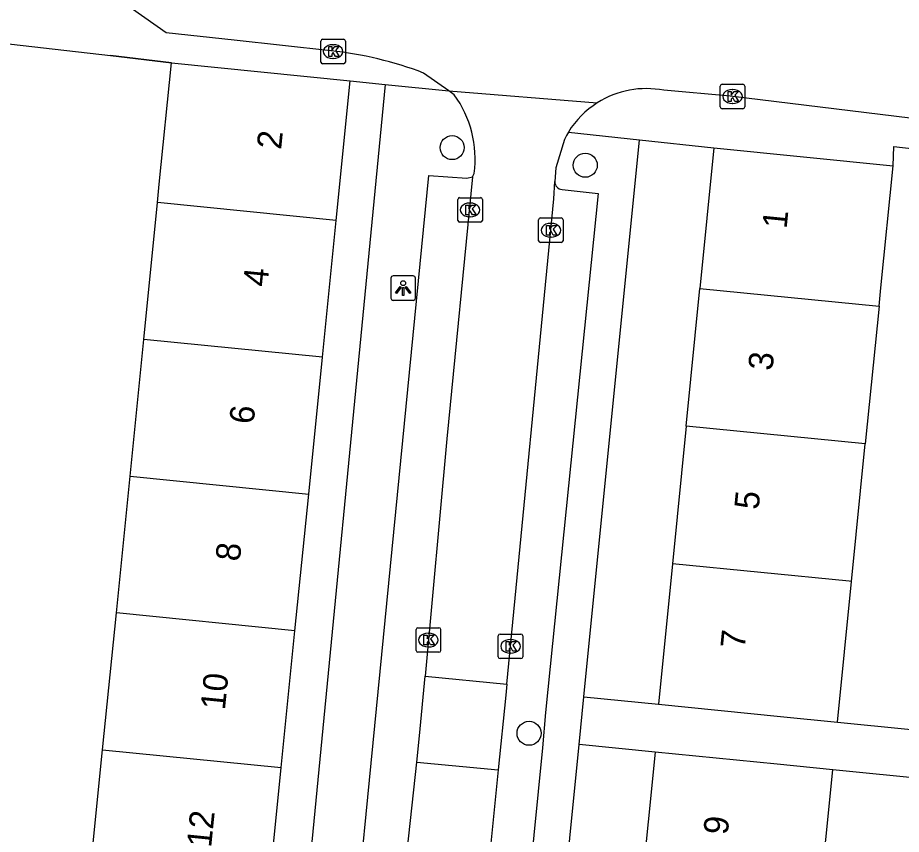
# Model space of a CAD drawing. Extents: x 162250 to 162654, y 380744 to 381605.
# Drawn here: x 162303.66 to 162339.7, y 380867.49 to 380900.78 of the extents above; entities that cross this region are included whole.
import ezdxf

# ---------------------------------------------------------------- set-up
doc = ezdxf.new("R2010")
doc.units = 0
for name, color, linetype in [('IMGEO_Boom', 7, 'Continuous'), ('IMGEO_Kolk', 7, 'Continuous'), ('IMGEO_Lichtpunt', 7, 'Continuous'), ('IMGEO_Muur', 7, 'Continuous'), ('IMGEO_Pand', 7, 'Continuous'), ('IMGEO_Pand_nummerreeks', 7, 'Continuous'), ('IMGEO_Rijbaan_lokaal_open', 7, 'Continuous'), ('IMGEO_Voetpad_open', 7, 'Continuous')]:
    doc.layers.add(name, color=color, linetype=linetype)

msp = doc.modelspace()

# ---------------------------------------------------------------- linework, layer by layer
at = {"layer": 'IMGEO_Boom'}
for centre in [(162321.376, 380895.484), (162326.808, 380894.764), (162324.515, 380871.605)]:
    msp.add_circle(centre, 0.489, dxfattribs=at)
at = {"layer": 'IMGEO_Kolk'}
for p, q in [((162316.022, 380898.974), (162316.022, 380899.826)), ((162316.097, 380899.9), (162316.949, 380899.9)), ((162316.51, 380899.68), (162316.535, 380899.68)), ((162317.023, 380899.826), (162317.023, 380898.974)), ((162316.533, 380899.12), (162316.508, 380899.12)), ((162316.949, 380898.9), (162316.097, 380898.9)), ((162332.314, 380897.143), (162332.314, 380897.995)), ((162332.389, 380898.069), (162333.241, 380898.069)), ((162332.802, 380897.849), (162332.827, 380897.849)), ((162333.315, 380897.995), (162333.315, 380897.143)), ((162332.825, 380897.289), (162332.8, 380897.289)), ((162333.241, 380897.069), (162332.389, 380897.069)), ((162321.609, 380892.517), (162321.609, 380893.369)), ((162321.684, 380893.443), (162322.536, 380893.443)), ((162322.097, 380893.223), (162322.122, 380893.223)), ((162322.61, 380893.369), (162322.61, 380892.517)), ((162322.536, 380892.443), (162321.684, 380892.443)), ((162322.12, 380892.663), (162322.095, 380892.663)), ((162324.905, 380891.689), (162324.905, 380892.541)), ((162324.98, 380892.615), (162325.832, 380892.615)), ((162325.906, 380892.541), (162325.906, 380891.689)), ((162325.393, 380892.395), (162325.418, 380892.395)), ((162325.416, 380891.835), (162325.391, 380891.835)), ((162325.832, 380891.615), (162324.98, 380891.615)), ((162319.909, 380874.981), (162319.909, 380875.833)), ((162319.984, 380875.907), (162320.836, 380875.907)), ((162320.91, 380875.833), (162320.91, 380874.981)), ((162320.397, 380875.687), (162320.422, 380875.687)), ((162323.259, 380874.725), (162323.259, 380875.577)), ((162323.334, 380875.651), (162324.186, 380875.651)), ((162324.26, 380875.577), (162324.26, 380874.725)), ((162320.42, 380875.127), (162320.395, 380875.127)), ((162323.747, 380875.431), (162323.772, 380875.431)), ((162320.836, 380874.907), (162319.984, 380874.907)), ((162323.77, 380874.871), (162323.745, 380874.871)), ((162324.186, 380874.651), (162323.334, 380874.651))]:
    msp.add_line(p, q, dxfattribs=at)
for points in [[(162316.022, 380898.974), (162316.022, 380899.826)], [(162316.097, 380899.9), (162316.949, 380899.9)], [(162317.023, 380899.826), (162317.023, 380898.974)], [(162316.343, 380899.6), (162316.466, 380899.6), (162316.466, 380899.449), (162316.596, 380899.6), (162316.76, 380899.6), (162316.614, 380899.449), (162316.767, 380899.2), (162316.615, 380899.2), (162316.53, 380899.364), (162316.466, 380899.297), (162316.466, 380899.2), (162316.343, 380899.2), (162316.343, 380899.6)], [(162316.949, 380898.9), (162316.097, 380898.9)], [(162332.314, 380897.143), (162332.314, 380897.995)], [(162332.389, 380898.069), (162333.241, 380898.069)], [(162333.315, 380897.995), (162333.315, 380897.143)], [(162332.635, 380897.769), (162332.758, 380897.769), (162332.758, 380897.618), (162332.888, 380897.769), (162333.052, 380897.769), (162332.906, 380897.618), (162333.059, 380897.369), (162332.907, 380897.369), (162332.822, 380897.533), (162332.758, 380897.466), (162332.758, 380897.369), (162332.635, 380897.369), (162332.635, 380897.769)], [(162333.241, 380897.069), (162332.389, 380897.069)], [(162321.609, 380892.517), (162321.609, 380893.369)], [(162321.684, 380893.443), (162322.536, 380893.443)], [(162321.93, 380893.143), (162322.053, 380893.143), (162322.053, 380892.992), (162322.183, 380893.143), (162322.347, 380893.143), (162322.201, 380892.992), (162322.354, 380892.743), (162322.202, 380892.743), (162322.117, 380892.907), (162322.053, 380892.84), (162322.053, 380892.743), (162321.93, 380892.743), (162321.93, 380893.143)], [(162322.61, 380893.369), (162322.61, 380892.517)], [(162322.536, 380892.443), (162321.684, 380892.443)], [(162324.905, 380891.689), (162324.905, 380892.541)], [(162324.98, 380892.615), (162325.832, 380892.615)], [(162325.906, 380892.541), (162325.906, 380891.689)], [(162325.226, 380892.315), (162325.349, 380892.315), (162325.349, 380892.164), (162325.479, 380892.315), (162325.643, 380892.315), (162325.497, 380892.164), (162325.65, 380891.915), (162325.498, 380891.915), (162325.413, 380892.079), (162325.349, 380892.012), (162325.349, 380891.915), (162325.226, 380891.915), (162325.226, 380892.315)], [(162325.832, 380891.615), (162324.98, 380891.615)], [(162319.909, 380874.981), (162319.909, 380875.833)], [(162319.984, 380875.907), (162320.836, 380875.907)], [(162320.91, 380875.833), (162320.91, 380874.981)], [(162320.23, 380875.607), (162320.353, 380875.607), (162320.353, 380875.456), (162320.483, 380875.607), (162320.647, 380875.607), (162320.501, 380875.456), (162320.654, 380875.207), (162320.502, 380875.207), (162320.417, 380875.371), (162320.353, 380875.304), (162320.353, 380875.207), (162320.23, 380875.207), (162320.23, 380875.607)], [(162323.259, 380874.725), (162323.259, 380875.577)], [(162323.334, 380875.651), (162324.186, 380875.651)], [(162324.26, 380875.577), (162324.26, 380874.725)], [(162323.58, 380875.351), (162323.703, 380875.351), (162323.703, 380875.2), (162323.833, 380875.351), (162323.997, 380875.351), (162323.851, 380875.2), (162324.004, 380874.951), (162323.852, 380874.951), (162323.767, 380875.115), (162323.703, 380875.048), (162323.703, 380874.951), (162323.58, 380874.951), (162323.58, 380875.351)], [(162320.836, 380874.907), (162319.984, 380874.907)], [(162324.186, 380874.651), (162323.334, 380874.651)]]:
    msp.add_lwpolyline(points, dxfattribs=at)
for centre, start, end in [((162316.099, 380899.824), 91.552, 178.448), ((162316.099, 380899.824), 91.552, 178.448), ((162316.947, 380899.824), 1.552, 88.448), ((162316.947, 380899.824), 1.552, 88.448), ((162316.099, 380898.976), 181.552, 268.448), ((162316.099, 380898.976), 181.552, 268.448), ((162316.947, 380898.976), 271.552, 358.448), ((162316.947, 380898.976), 271.552, 358.448), ((162332.391, 380897.993), 91.552, 178.448), ((162332.391, 380897.993), 91.552, 178.448), ((162333.239, 380897.993), 1.552, 88.448), ((162333.239, 380897.993), 1.552, 88.448), ((162332.391, 380897.145), 181.552, 268.448), ((162332.391, 380897.145), 181.552, 268.448), ((162333.239, 380897.145), 271.552, 358.448), ((162333.239, 380897.145), 271.552, 358.448), ((162321.686, 380893.367), 91.552, 178.448), ((162321.686, 380893.367), 91.552, 178.448), ((162322.534, 380893.367), 1.552, 88.448), ((162322.534, 380893.367), 1.552, 88.448), ((162321.686, 380892.519), 181.552, 268.448), ((162321.686, 380892.519), 181.552, 268.448), ((162322.534, 380892.519), 271.552, 358.448), ((162322.534, 380892.519), 271.552, 358.448), ((162324.982, 380892.539), 91.552, 178.448), ((162324.982, 380892.539), 91.552, 178.448), ((162325.83, 380892.539), 1.552, 88.448), ((162325.83, 380892.539), 1.552, 88.448), ((162324.982, 380891.691), 181.552, 268.448), ((162324.982, 380891.691), 181.552, 268.448), ((162325.83, 380891.691), 271.552, 358.448), ((162325.83, 380891.691), 271.552, 358.448), ((162319.986, 380875.831), 91.552, 178.448), ((162319.986, 380875.831), 91.552, 178.448), ((162320.834, 380875.831), 1.552, 88.448), ((162320.834, 380875.831), 1.552, 88.448), ((162323.336, 380875.575), 91.552, 178.448), ((162323.336, 380875.575), 91.552, 178.448), ((162324.184, 380875.575), 1.552, 88.448), ((162324.184, 380875.575), 1.552, 88.448), ((162319.986, 380874.983), 181.552, 268.448), ((162319.986, 380874.983), 181.552, 268.448), ((162320.834, 380874.983), 271.552, 358.448), ((162320.834, 380874.983), 271.552, 358.448), ((162323.336, 380874.727), 181.552, 268.448), ((162323.336, 380874.727), 181.552, 268.448), ((162324.184, 380874.727), 271.552, 358.448), ((162324.184, 380874.727), 271.552, 358.448)]:
    msp.add_arc(centre, 0.0765, start, end, dxfattribs=at)
for centre, major_axis, ratio, start_param, end_param in [((162316.509, 380899.4), (-0.387, 0.002), 0.722429, 4.712389, 7.853982), ((162316.534, 380899.4), (-0.39, 0.002), 0.717154, 1.570796, 4.712389), ((162332.801, 380897.569), (-0.387, 0.002), 0.722429, 4.712389, 7.853982), ((162332.826, 380897.569), (-0.39, 0.002), 0.717154, 1.570796, 4.712389), ((162322.096, 380892.943), (-0.387, 0.002), 0.722429, 4.712389, 7.853982), ((162322.121, 380892.943), (-0.39, 0.002), 0.717154, 1.570796, 4.712389), ((162325.392, 380892.115), (-0.387, 0.002), 0.722429, 4.712389, 7.853982), ((162325.417, 380892.115), (-0.39, 0.002), 0.717154, 1.570796, 4.712389), ((162320.396, 380875.407), (-0.387, 0.002), 0.722429, 4.712389, 7.853982), ((162320.421, 380875.407), (-0.39, 0.002), 0.717154, 1.570796, 4.712389), ((162323.746, 380875.151), (-0.387, 0.002), 0.722429, 4.712389, 7.853982), ((162323.771, 380875.151), (-0.39, 0.002), 0.717154, 1.570796, 4.712389)]:
    msp.add_ellipse(centre, major_axis=major_axis, ratio=ratio, start_param=start_param, end_param=end_param, dxfattribs=at)
at = {"layer": 'IMGEO_Lichtpunt'}
for p, q in [((162319.785, 380890.254), (162318.977, 380890.254)), ((162319.785, 380890.254), (162318.977, 380890.254)), ((162318.883, 380890.159), (162318.883, 380889.352)), ((162318.883, 380890.159), (162318.883, 380889.352)), ((162319.879, 380889.352), (162319.879, 380890.159)), ((162319.879, 380889.352), (162319.879, 380890.159)), ((162318.977, 380889.258), (162319.785, 380889.258)), ((162318.977, 380889.258), (162319.785, 380889.258))]:
    msp.add_line(p, q, dxfattribs=at)
for points in [[(162319.257, 380889.823), (162319.296, 380889.795), (162319.108, 380889.533), (162319.07, 380889.56), (162319.257, 380889.823)], [(162319.359, 380889.775), (162319.406, 380889.775), (162319.406, 380889.453), (162319.359, 380889.453), (162319.359, 380889.775)], [(162319.469, 380889.795), (162319.507, 380889.822), (162319.694, 380889.56), (162319.655, 380889.532), (162319.469, 380889.795)]]:
    msp.add_lwpolyline(points, dxfattribs=at)
msp.add_circle((162319.382, 380889.957), 0.0994, dxfattribs=at)
for centre, start, end in [((162318.977, 380890.159), 90, 180), ((162318.977, 380890.159), 90, 180), ((162319.785, 380890.159), 0, 90), ((162319.785, 380890.159), 0, 90), ((162318.977, 380889.352), 180, 270), ((162318.977, 380889.352), 180, 270), ((162319.785, 380889.352), 270, 0), ((162319.785, 380889.352), 270, 360)]:
    msp.add_arc(centre, 0.0946, start, end, dxfattribs=at)
at = {"layer": 'IMGEO_Muur'}
msp.add_lwpolyline([(162309.931, 380898.942), (162307.447, 380899.233)], dxfattribs=at)
at = {"layer": 'IMGEO_Pand'}
for points in [[(162309.359, 380893.244), (162309.435, 380893.999), (162309.931, 380898.942)], [(162309.931, 380898.942), (162317.217, 380898.211)], [(162316.646, 380892.514), (162317.217, 380898.211)], [(162332.054, 380895.474), (162331.483, 380889.744)], [(162332.054, 380895.474), (162339.361, 380894.746)], [(162338.79, 380889.014), (162338.865, 380889.771), (162339.361, 380894.746)], [(162308.8, 380887.667), (162309.359, 380893.244)], [(162316.646, 380892.514), (162309.359, 380893.244)], [(162316.086, 380886.937), (162316.646, 380892.514)], [(162330.923, 380884.132), (162331.483, 380889.744)], [(162331.483, 380889.744), (162338.79, 380889.014)], [(162338.79, 380889.014), (162338.23, 380883.402)], [(162308.241, 380882.089), (162308.8, 380887.667)], [(162316.086, 380886.937), (162308.8, 380887.667)], [(162315.527, 380881.36), (162316.086, 380886.937)], [(162330.923, 380884.132), (162330.363, 380878.521)], [(162338.23, 380883.402), (162330.923, 380884.132)], [(162337.67, 380877.791), (162338.23, 380883.402)], [(162307.682, 380876.513), (162308.241, 380882.089)], [(162308.241, 380882.089), (162315.527, 380881.36)], [(162314.968, 380875.783), (162315.527, 380881.36)], [(162330.363, 380878.521), (162329.792, 380872.791)], [(162337.67, 380877.791), (162337.566, 380877.801), (162330.363, 380878.521)], [(162337.099, 380872.063), (162337.67, 380877.791)], [(162307.122, 380870.936), (162307.682, 380876.513)], [(162314.968, 380875.783), (162307.682, 380876.513)], [(162314.409, 380870.206), (162314.968, 380875.783)], [(162329.792, 380872.791), (162334.768, 380872.295), (162337.099, 380872.063)], [(162306.565, 380865.378), (162307.122, 380870.936)], [(162307.122, 380870.936), (162314.409, 380870.206)], [(162329.66, 380870.837), (162329.088, 380865.149)], [(162336.901, 380870.115), (162334.636, 380870.341), (162329.66, 380870.837)], [(162313.849, 380864.627), (162314.409, 380870.206)], [(162336.334, 380864.429), (162336.901, 380870.115)]]:
    msp.add_lwpolyline(points, dxfattribs=at)
at = {"layer": 'IMGEO_Rijbaan_lokaal_open'}
for points in [[(162316.431, 380899.429), (162312.494, 380899.87), (162309.716, 380900.169), (162305.327, 380903.261), (162304.299, 380903.584), (162300.415, 380904.048), (162289.869, 380905.312)], [(162321.245, 380897.797), (162320.215, 380898.526)], [(162359.977, 380896.391), (162356.902, 380896.747), (162354.653, 380897.008), (162353.19, 380897.171), (162349.392, 380897.594), (162345.711, 380898.004), (162345.487, 380898.034), (162344.942, 380898.106), (162344.722, 380898.057), (162344.512, 380898.048), (162341.28, 380896.536), (162332.717, 380897.582), (162330.019, 380897.82)], [(162321.245, 380897.797), (162327.3, 380897.311)], [(162321.467, 380897.64), (162321.245, 380897.797)], [(162325.956, 380895.821), (162325.602, 380894.662), (162325.569, 380894.099)], [(162322.208, 380894.288), (162321.165, 380883.616), (162320.276, 380873.933)], [(162322.208, 380894.288), (162322.274, 380894.435)], [(162323.609, 380873.614), (162325.529, 380893.393), (162325.569, 380894.099)], [(162319.937, 380870.429), (162320.053, 380871.499), (162320.276, 380873.933)], [(162320.276, 380873.933), (162323.609, 380873.614)], [(162323.609, 380873.614), (162323.565, 380873.159), (162323.26, 380870.111)], [(162316.769, 380839.988), (162317.589, 380847.669), (162318.936, 380861.173), (162319.937, 380870.429)], [(162319.937, 380870.429), (162323.26, 380870.111)], [(162323.26, 380870.111), (162321.48, 380852.317), (162320.213, 380838.831), (162319.086, 380828.026)]]:
    msp.add_lwpolyline(points, dxfattribs=at)
for centre, radius, start, end in [((162314.876, 380884.534), 14.976, 69.1152, 84.0411), ((162329.298, 380894.153), 3.737, 78.8808, 122.3254), ((162317.892, 380895.036), 4.423, 352.1963, 36.0696), ((162329.302, 380894.153), 3.74, 122.3717, 148.2572), ((162329.852, 380893.854), 4.364, 148.7163, 153.207)]:
    msp.add_arc(centre, radius, start, end, dxfattribs=at)
at = {"layer": 'IMGEO_Voetpad_open'}
for points in [[(162299.23, 380900.181), (162307.447, 380899.233), (162309.931, 380898.942)], [(162317.217, 380898.211), (162318.65, 380898.061)], [(162318.65, 380898.061), (162315.15, 380861.984), (162309.116, 380802.856), (162307.67, 380803.003)], [(162318.65, 380898.061), (162321.245, 380897.797)], [(162326.122, 380896.12), (162329.014, 380895.802)], [(162326.75, 380873.094), (162329.014, 380895.802)], [(162329.014, 380895.802), (162332.054, 380895.474)], [(162339.361, 380894.746), (162339.398, 380895.532), (162350.689, 380894.244)], [(162316.236, 380840.651), (162315.17, 380840.746), (162320.433, 380894.347), (162321.981, 380894.236), (162322.208, 380894.288)], [(162325.864, 380893.781), (162327.336, 380893.62), (162325.189, 380872.449), (162325.066, 380871.015), (162320.821, 380828.279), (162319.819, 380828.412)], [(162337.099, 380872.063), (162348.708, 380870.908), (162348.984, 380874.212)], [(162326.556, 380871.147), (162326.75, 380873.094)], [(162326.75, 380873.094), (162329.792, 380872.791)], [(162321.509, 380803.901), (162319.92, 380804.066), (162319.973, 380805.135), (162326.556, 380871.147)], [(162329.66, 380870.837), (162326.556, 380871.147)], [(162348.221, 380865.572), (162348.503, 380868.957), (162336.901, 380870.115)]]:
    msp.add_lwpolyline(points, dxfattribs=at)
msp.add_arc((162325.876, 380894.088), 0.308, 177.9999, 267.7026, dxfattribs=at)

# ---------------------------------------------------------------- texts
at = {"layer": 'IMGEO_Pand_nummerreeks'}
for s, rotation, p in [('2', 84.2738, (162314.402, 380895.386)), ('1', 84.3052, (162335.019, 380892.153)), ('4', 84.2738, (162313.84, 380889.788)), ('3', 84.3052, (162334.442, 380886.368)), ('6', 84.2738, (162313.279, 380884.187)), ('5', 84.3052, (162333.877, 380880.697)), ('8', 84.2738, (162312.717, 380878.591)), ('7', 84.3052, (162333.311, 380875.027)), ('10', 84.2738, (162312.109, 380872.531)), ('12', 84.2738, (162311.548, 380866.925)), ('9', 84.2592, (162332.616, 380867.441))]:
    msp.add_text(s, height=1, rotation=rotation, dxfattribs=at).set_placement(p)

doc.saveas('drawing.dxf')
